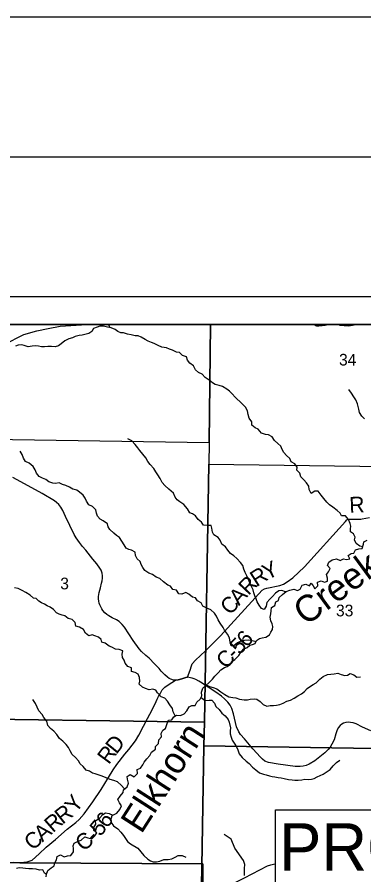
# Model space of a CAD drawing. Extents: x -20.5 to 34, y -66 to 23.9.
# Drawn here: x 5.279 to 6.523, y 18.93 to 22 of the extents above; entities that cross this region are included whole.
import ezdxf

# ---------------------------------------------------------------- set-up
doc = ezdxf.new("R2010")
doc.units = 0
for name, color, linetype in [('Default', 7, 'Continuous'), ('GM_X_County_Road_Text', 7, 'Continuous'), ('GM_X_County_Text', 7, 'Continuous'), ('GM_X_Minor_Lake', 7, 'Continuous'), ('GM_X_Minor_River_Text', 7, 'Continuous'), ('GM_X_State_Route', 7, 'Continuous'), ('GM_X_Township_Road', 7, 'Continuous'), ('GM_X_Township_Road_Text', 7, 'Continuous'), ('GM_X_Township_Text', 7, 'Continuous'), ('SH_Border', 7, 'Continuous'), ('SH_Cut_Line', 7, 'Continuous'), ('SH_Data', 7, 'Continuous'), ('SH_Text', 7, 'Continuous')]:
    doc.layers.add(name, color=color, linetype=linetype)

msp = doc.modelspace()

# ---------------------------------------------------------------- linework, layer by layer
at = {"layer": 'Default'}
for points in [[(2.1, 20.9), (8.9, 20.9), (8.9, 14.1), (2.1, 14.1)], [(5.9729, 20.9), (4.9548, 20.9), (4.9488, 20.4926), (5.968, 20.4777)], [(6.961, 20.9), (5.9729, 20.9), (5.968, 20.4777), (5.9663, 20.3996), (6.9585, 20.3868)]]:
    msp.add_lwpolyline(points, close=True, dxfattribs=at)
for points in [[(8.3774, 18.8452), (8.7292, 18.8379), (8.9, 18.8361), (8.9, 20.9), (2.1, 20.9), (2.1, 19.024), (2.1138, 19.0238), (2.8866, 19.0123), (2.9847, 19.0125), (3.3332, 19.0103), (5.1839, 18.9738), (5.2343, 18.9736), (5.2893, 18.9731), (5.9456, 18.969), (5.9451, 18.8918), (6.0429, 18.8899), (6.0928, 18.889), (6.2064, 18.8869)], [(6.2064, 18.8869), (6.0928, 18.889), (6.0429, 18.8899), (5.9451, 18.8918), (5.9456, 18.969), (5.2893, 18.9731), (5.2343, 18.9736), (5.1839, 18.9738), (3.3332, 19.0103), (2.9847, 19.0125), (2.8866, 19.0123), (2.8861, 18.9025), (2.8826, 18.5075), (2.8801, 18.0269), (2.88, 18.0245)]]:
    msp.add_lwpolyline(points, dxfattribs=at)
at = {"layer": 'GM_X_County_Text'}
for points in [[(4.9459, 20.818), (4.9557, 20.8151), (5.1026, 20.8066), (5.1363, 20.8076), (5.15, 20.8095), (5.2334, 20.8288), (5.3038, 20.8638), (5.3498, 20.8773), (5.3902, 20.8851)], [(5.3902, 20.8851), (5.4336, 20.8934), (5.5299, 20.9)], [(6.345, 20.9), (6.3465, 20.8987), (6.3501, 20.896), (6.3534, 20.8949), (6.3611, 20.895), (6.3729, 20.8959), (6.3834, 20.8976), (6.3946, 20.9)], [(6.4354, 20.898), (6.4688, 20.8956), (6.4949, 20.9)], [(6.0946, 18.9277), (6.0951, 18.9521), (6.0953, 18.9667), (6.0907, 18.9815), (6.0603, 19.0257), (6.0466, 19.0569), (6.0218, 19.0744)]]:
    msp.add_lwpolyline(points, dxfattribs=at)
at = {"layer": 'GM_X_Minor_Lake'}
for points in [[(5.968, 20.4777), (5.9663, 20.3996), (5.9508, 19.4767), (4.9304, 19.491), (4.9488, 20.4926)], [(5.9663, 20.3996), (6.9585, 20.3868), (6.9446, 19.3763), (5.9493, 19.3913), (5.9508, 19.4767)], [(4.9304, 19.491), (5.9508, 19.4767), (5.9493, 19.3913), (5.9332, 18.4574), (4.9118, 18.4742)]]:
    msp.add_lwpolyline(points, close=True, dxfattribs=at)
msp.add_lwpolyline([(6.9358, 18.3792), (6.9356, 18.3607), (5.9313, 18.3709), (5.9332, 18.4574), (5.9493, 19.3913), (6.9446, 19.3763), (6.9427, 19.1628)], dxfattribs=at)
at = {"layer": 'GM_X_Minor_River_Text'}
msp.add_line((5.6113, 20.8889), (5.6088, 20.9), dxfattribs=at)
for points in [[(6.5188, 20.1044), (6.508, 20.1059), (6.4953, 20.1155), (6.489, 20.1295), (6.4919, 20.139), (6.4856, 20.1503), (6.4749, 20.1581), (6.4747, 20.1679), (6.4761, 20.1774), (6.4736, 20.188), (6.4673, 20.2023), (6.4564, 20.2154), (6.4428, 20.2148), (6.4381, 20.2246), (6.4265, 20.2343), (6.4119, 20.2454), (6.3996, 20.2547), (6.3896, 20.2633), (6.3795, 20.2768), (6.3698, 20.2891), (6.3585, 20.3026), (6.3464, 20.3032), (6.334, 20.2946), (6.3261, 20.3093), (6.3252, 20.321), (6.317, 20.3334), (6.307, 20.3439), (6.2962, 20.3539), (6.2933, 20.3679), (6.2825, 20.3784), (6.2838, 20.3886), (6.2752, 20.4014), (6.2622, 20.408), (6.2567, 20.42), (6.2448, 20.4308), (6.2351, 20.4413), (6.2292, 20.4518), (6.2248, 20.4639), (6.2144, 20.4744), (6.2017, 20.4844), (6.1939, 20.4972), (6.1805, 20.5045), (6.1698, 20.5062), (6.1553, 20.5113), (6.1437, 20.5248), (6.1326, 20.5303), (6.1214, 20.54), (6.1209, 20.551), (6.1115, 20.5645), (6.1079, 20.5781), (6.1058, 20.5902), (6.0983, 20.6041), (6.0848, 20.6168), (6.0616, 20.6399), (6.0501, 20.6511), (6.0408, 20.6608), (6.0308, 20.6682), (6.0162, 20.6778), (6.0036, 20.6818), (5.9895, 20.6854), (5.9795, 20.6905), (5.9684, 20.7006), (5.9542, 20.7098), (5.9426, 20.7218), (5.9299, 20.7276), (5.9184, 20.7373), (5.9124, 20.752), (5.899, 20.7613), (5.8901, 20.7721), (5.8865, 20.7838), (5.872, 20.7889), (5.8615, 20.7993), (5.8513, 20.8003), (5.8367, 20.8077), (5.8256, 20.8117), (5.8153, 20.8157), (5.7986, 20.8192), (5.7852, 20.825), (5.7706, 20.8312), (5.7607, 20.8352), (5.7496, 20.84), (5.7385, 20.8463), (5.7247, 20.8547), (5.7132, 20.8591), (5.7022, 20.8597), (5.6885, 20.8625), (5.6755, 20.8653), (5.6606, 20.8696), (5.6508, 20.8702), (5.6408, 20.8746), (5.6312, 20.8817), (5.6163, 20.8879), (5.603, 20.8907), (5.5892, 20.8935), (5.5763, 20.894), (5.5661, 20.8901), (5.5537, 20.8849), (5.5478, 20.8746), (5.5361, 20.8676), (5.5123, 20.8618), (5.5013, 20.8605)], [(5.5013, 20.8605), (5.4873, 20.8573), (5.4775, 20.8522), (5.4647, 20.8485), (5.45, 20.8415), (5.4377, 20.8303), (5.4279, 20.824), (5.4162, 20.8204), (5.4021, 20.8213), (5.39, 20.8211), (5.3775, 20.8201), (5.3668, 20.82), (5.3562, 20.8217), (5.3467, 20.8234), (5.3338, 20.8217), (5.3194, 20.8203), (5.3052, 20.825), (5.2953, 20.8275), (5.2832, 20.8262), (5.2734, 20.8218)], [(6.5254, 20.5622), (6.5158, 20.5719), (6.5068, 20.5851), (6.5047, 20.5972), (6.4998, 20.6161), (6.4939, 20.6304), (6.4865, 20.6413), (6.4787, 20.6544), (6.4686, 20.6668)], [(6.242, 19.9426), (6.2286, 19.9472), (6.2172, 19.947), (6.206, 19.9377), (6.1948, 19.9258), (6.185, 19.9169), (6.175, 19.905), (6.1726, 19.8913), (6.1655, 19.8801), (6.156, 19.883), (6.1478, 19.895), (6.1404, 19.9067), (6.1364, 19.9176), (6.1321, 19.9289), (6.1285, 19.9395), (6.1253, 19.95), (6.1186, 19.9647), (6.1134, 19.9756), (6.1083, 19.9892), (6.1031, 20.0005), (6.0969, 20.0118), (6.0917, 20.0239), (6.0881, 20.0371), (6.0807, 20.0476), (6.0676, 20.0618), (6.0568, 20.0722), (6.0449, 20.08), (6.0344, 20.0916), (6.0266, 20.104), (6.0139, 20.1129), (6.0072, 20.1275), (6.0006, 20.1373), (5.9853, 20.1465), (5.9794, 20.1563), (5.9777, 20.1703), (5.9752, 20.1805), (5.9615, 20.1799), (5.9482, 20.182), (5.9408, 20.1921), (5.9289, 20.2017), (5.9184, 20.2152), (5.9084, 20.2219), (5.8985, 20.2259), (5.8899, 20.2398), (5.8775, 20.2555), (5.8629, 20.2648), (5.8529, 20.2726), (5.8459, 20.2823), (5.8396, 20.2963), (5.8238, 20.3108), (5.8095, 20.3231), (5.7991, 20.3347), (5.7924, 20.3486), (5.7838, 20.3621), (5.7764, 20.3718), (5.7694, 20.3839), (5.7566, 20.3981), (5.7485, 20.4097), (5.7407, 20.4221), (5.7306, 20.4356), (5.719, 20.4483), (5.7123, 20.4584), (5.7026, 20.4708), (5.6903, 20.4835), (5.6765, 20.4908)], [(6.136, 19.7642), (6.1173, 19.7689), (6.1074, 19.7695), (6.0941, 19.7689), (6.0835, 19.7676), (6.0696, 19.7606), (6.0565, 19.7501), (6.0466, 19.7499), (6.043, 19.7628), (6.0412, 19.7779), (6.0338, 19.7914), (6.0225, 19.8057), (6.0178, 19.8155), (6.0069, 19.8312), (5.9999, 19.8429), (5.9943, 19.8557), (5.9866, 19.8665), (5.9738, 19.8785), (5.9593, 19.8847), (5.9451, 19.892), (5.9389, 19.9029), (5.9262, 19.9111), (5.9184, 19.9219), (5.9085, 19.9233), (5.8954, 19.9341), (5.8839, 19.94), (5.8704, 19.934), (5.8593, 19.9361), (5.8504, 19.9493), (5.8374, 19.9506), (5.8292, 19.9637), (5.8197, 19.967), (5.8047, 19.9792), (5.7912, 19.99), (5.7782, 19.9959), (5.7644, 20.0048), (5.7514, 20.0091), (5.7368, 20.0187), (5.7298, 20.0296), (5.7239, 20.0409), (5.7207, 20.0515), (5.7095, 20.0604), (5.704, 20.0724), (5.7027, 20.0849), (5.6893, 20.0923), (5.6797, 20.094), (5.6698, 20.0996), (5.6631, 20.1112), (5.6546, 20.1243), (5.6464, 20.1371), (5.6352, 20.1441), (5.6256, 20.1531), (5.6121, 20.1654), (5.6059, 20.1751), (5.6034, 20.1857), (5.5876, 20.1972), (5.5777, 20.2024), (5.568, 20.2136), (5.564, 20.2245), (5.5612, 20.2366), (5.5496, 20.2486), (5.5366, 20.2544), (5.5276, 20.2672), (5.5232, 20.2785), (5.5166, 20.289), (5.5035, 20.2998), (5.4939, 20.3064), (5.4794, 20.3108), (5.4675, 20.3178), (5.4542, 20.3232), (5.4416, 20.3276), (5.4301, 20.3331), (5.4176, 20.3306), (5.4073, 20.3319), (5.3936, 20.337), (5.3824, 20.3444), (5.3702, 20.3492), (5.3579, 20.3562), (5.349, 20.3682), (5.3439, 20.3791), (5.3372, 20.3919), (5.3226, 20.4038), (5.3096, 20.4096), (5.3018, 20.4209), (5.2978, 20.4341), (5.2907, 20.4469)], [(5.817, 19.4714), (5.8221, 19.4833), (5.8346, 19.4842), (5.8409, 19.4957), (5.8511, 19.5012), (5.8647, 19.5007), (5.8787, 19.5066), (5.8876, 19.517), (5.8961, 19.5308), (5.9059, 19.5355), (5.9177, 19.5357), (5.9236, 19.5483), (5.9352, 19.5584), (5.9422, 19.5702), (5.9404, 19.5831), (5.9447, 19.5976), (5.9556, 19.6077), (5.9679, 19.6185), (5.9799, 19.6308), (5.9884, 19.6404), (6.0004, 19.6528), (6.0101, 19.6632), (6.0229, 19.6718), (6.0327, 19.6761), (6.0428, 19.6823), (6.0483, 19.6923), (6.0596, 19.7008), (6.0738, 19.7147), (6.0804, 19.7243), (6.0912, 19.737), (6.1037, 19.744), (6.1138, 19.7514), (6.1236, 19.7546), (6.1334, 19.7582), (6.1378, 19.7681), (6.1487, 19.7759), (6.1585, 19.7787), (6.1714, 19.7801), (6.1842, 19.7886), (6.1893, 19.7982), (6.1952, 19.8082), (6.1966, 19.8188), (6.1941, 19.8286), (6.1894, 19.8388), (6.1869, 19.852), (6.1886, 19.8646), (6.1899, 19.8745), (6.1912, 19.887), (6.2029, 19.894), (6.2068, 19.907), (6.2166, 19.9117), (6.2191, 19.9224), (6.2307, 19.9332), (6.2442, 19.9444), (6.2574, 19.9492), (6.271, 19.9525), (6.2844, 19.9474), (6.2945, 19.9529), (6.3019, 19.9663), (6.3144, 19.9703), (6.3274, 19.9648), (6.3337, 19.9744), (6.3407, 19.9646), (6.3466, 19.953), (6.3574, 19.9649), (6.3568, 19.9774), (6.3696, 19.9822), (6.3818, 19.9771), (6.392, 19.9814), (6.3922, 19.9913), (6.3886, 20.0053), (6.3956, 20.0149), (6.4019, 20.0263), (6.3926, 20.0368), (6.3966, 20.049), (6.4086, 20.0576), (6.4245, 20.0613), (6.4375, 20.0554), (6.4495, 20.0605), (6.4602, 20.0584), (6.4719, 20.0605), (6.4664, 20.0726), (6.4769, 20.08), (6.4864, 20.0809), (6.493, 20.0931), (6.5047, 20.0971), (6.5169, 20.0977), (6.5212, 20.1129), (6.5222, 20.1224), (6.5346, 20.1272)], [(5.8459, 19.4984), (5.8391, 19.5128), (5.8366, 19.5249), (5.8273, 19.538), (5.8191, 19.5515), (5.8094, 19.562), (5.7953, 19.5674), (5.7833, 19.5809), (5.7763, 19.5906), (5.766, 19.5939), (5.7527, 19.5921), (5.7393, 19.5972), (5.729, 19.602), (5.7171, 19.612), (5.7199, 19.6231), (5.7182, 19.6363), (5.7131, 19.648), (5.7023, 19.6543), (5.6893, 19.6579), (5.6891, 19.6708), (5.6758, 19.6751), (5.6672, 19.6878), (5.6632, 19.698), (5.6574, 19.7082), (5.6557, 19.7195), (5.6581, 19.7317), (5.6455, 19.7368), (5.6326, 19.7374), (5.6195, 19.7451), (5.6092, 19.7487), (5.5954, 19.7591), (5.5832, 19.7623), (5.5811, 19.7722), (5.5715, 19.78), (5.5581, 19.7851), (5.5486, 19.7891), (5.5361, 19.7851), (5.5249, 19.7944), (5.5179, 19.8079), (5.5029, 19.816), (5.4896, 19.8196), (5.4878, 19.8332), (5.4763, 19.844), (5.4629, 19.8476), (5.4506, 19.8573), (5.4411, 19.8594), (5.4304, 19.8634), (5.4208, 19.8681), (5.4096, 19.8797), (5.3973, 19.8879), (5.387, 19.8926), (5.3774, 19.8989), (5.3674, 19.9037), (5.3578, 19.9096), (5.3474, 19.9185), (5.3379, 19.9206), (5.326, 19.9311), (5.3106, 19.9403), (5.2972, 19.9473), (5.2834, 19.9543), (5.2697, 19.9575)], [(5.9575, 19.6094), (5.9689, 19.6045), (5.9823, 19.6005), (5.996, 19.5958), (6.0103, 19.5843), (6.0241, 19.5754), (6.0383, 19.5669), (6.0531, 19.5641), (6.0638, 19.5635), (6.0771, 19.5592), (6.0939, 19.5565), (6.1053, 19.5559), (6.1155, 19.5587), (6.1288, 19.5601), (6.1387, 19.5583), (6.1506, 19.5506), (6.161, 19.5401), (6.1748, 19.5331), (6.1869, 19.5364), (6.1983, 19.5362), (6.2097, 19.5368), (6.221, 19.54), (6.2331, 19.5447), (6.2459, 19.551), (6.2595, 19.555), (6.273, 19.5621), (6.2862, 19.5707), (6.2986, 19.5777), (6.3098, 19.5858), (6.3199, 19.5966), (6.3311, 19.6052), (6.3413, 19.611), (6.3514, 19.6173), (6.3645, 19.6304), (6.3773, 19.6401), (6.3923, 19.6468), (6.4037, 19.6477), (6.4166, 19.6491), (6.4291, 19.6512), (6.4409, 19.6468), (6.4539, 19.6436), (6.4634, 19.6445), (6.4731, 19.65), (6.4865, 19.6461), (6.4973, 19.6379), (6.5102, 19.6381)], [(5.9388, 19.5645), (5.9538, 19.5541), (5.9675, 19.5551), (5.9774, 19.5553), (5.9874, 19.5437), (5.9914, 19.5327), (6.0034, 19.5212), (6.0138, 19.5088), (6.0258, 19.4984), (6.0358, 19.4861), (6.0398, 19.4763)], [(5.39, 19.4639), (5.3855, 19.4802), (5.3755, 19.4933), (5.3692, 19.5034), (5.3572, 19.5169), (5.3517, 19.5301), (5.3458, 19.5429), (5.3353, 19.5571)], [(5.6094, 19.1488), (5.6227, 19.143), (5.6366, 19.1511), (5.6481, 19.1638), (5.6536, 19.1772), (5.6466, 19.1877), (5.64, 19.1994), (5.6493, 19.2109), (5.6593, 19.2243), (5.6614, 19.2346), (5.6734, 19.245), (5.6785, 19.2584), (5.6749, 19.2723), (5.674, 19.2818), (5.6848, 19.2888), (5.699, 19.2803), (5.7113, 19.2926), (5.7095, 19.3063), (5.7223, 19.3118), (5.7297, 19.324), (5.7345, 19.3336), (5.7445, 19.3455), (5.7553, 19.357), (5.7612, 19.3692), (5.775, 19.3801), (5.776, 19.3896), (5.7864, 19.4), (5.7877, 19.4133), (5.7967, 19.424), (5.7961, 19.4362), (5.8016, 19.4476), (5.8117, 19.4531), (5.817, 19.4714)], [(6.0398, 19.4763), (6.044, 19.4559), (6.0427, 19.4448), (6.0428, 19.435), (6.0468, 19.4229), (6.0508, 19.412), (6.0574, 19.4015), (6.0655, 19.3875), (6.0706, 19.3774), (6.0761, 19.3631), (6.0865, 19.3492), (6.1003, 19.3369), (6.1111, 19.3279), (6.1238, 19.3152), (6.1356, 19.3052), (6.149, 19.2955), (6.1627, 19.2896), (6.1722, 19.2875), (6.184, 19.2847), (6.1939, 19.2822), (6.2034, 19.2804), (6.2151, 19.2787), (6.2265, 19.2773), (6.2368, 19.2752), (6.252, 19.2713), (6.2656, 19.2696), (6.2755, 19.2682), (6.2868, 19.2684), (6.3008, 19.2694), (6.3106, 19.2718), (6.3238, 19.2716), (6.3348, 19.2722), (6.3446, 19.2746), (6.3547, 19.2804), (6.366, 19.2848), (6.3765, 19.2903), (6.3878, 19.2976), (6.4016, 19.3073), (6.4124, 19.3204), (6.4247, 19.332), (6.4367, 19.3405)], [(5.6645, 19.2372), (5.6529, 19.2508), (5.6398, 19.2623), (5.6258, 19.267), (5.6132, 19.2706), (5.5991, 19.2765), (5.5839, 19.2827), (5.5732, 19.2871), (5.5592, 19.2918), (5.5493, 19.2943), (5.539, 19.3006), (5.5275, 19.305), (5.5164, 19.3173), (5.5053, 19.327), (5.499, 19.3383), (5.4883, 19.3495), (5.4767, 19.36), (5.4694, 19.3735), (5.4642, 19.3856), (5.455, 19.3964), (5.4438, 19.408), (5.4316, 19.4177), (5.4219, 19.4316), (5.4115, 19.4443), (5.3996, 19.454), (5.39, 19.4639)], [(5.3839, 18.9227), (5.3853, 18.9322), (5.3893, 18.9448), (5.4016, 18.9545), (5.4125, 18.9615), (5.4146, 18.9733), (5.4212, 18.9836), (5.4229, 18.9958), (5.4349, 19.0009), (5.4479, 18.9939), (5.4596, 18.9982), (5.4721, 18.9984), (5.4821, 19.0119), (5.4811, 19.024), (5.4802, 19.0335), (5.4842, 19.043), (5.4978, 19.05), (5.5094, 19.0536), (5.5221, 19.0656), (5.5335, 19.0623), (5.5468, 19.0591), (5.558, 19.0695), (5.5658, 19.0807), (5.5547, 19.0881), (5.5549, 19.0987), (5.5619, 19.1109), (5.561, 19.1227), (5.5759, 19.1343), (5.5867, 19.1462), (5.5965, 19.1513), (5.6094, 19.1488)], [(5.6197, 19.1443), (5.6157, 19.1296), (5.6171, 19.1171), (5.6248, 19.1051), (5.6401, 19.0939), (5.6517, 19.0827), (5.6613, 19.07), (5.6675, 19.0602), (5.6756, 19.0493), (5.686, 19.0411), (5.7119, 19.0248), (5.7224, 19.0125), (5.7339, 18.9994), (5.7481, 18.9856), (5.7577, 18.9797), (5.7672, 18.9768), (5.7789, 18.9762), (5.791, 18.979), (5.8049, 18.9842), (5.8208, 18.9848), (5.8336, 18.9876), (5.846, 18.9935), (5.8573, 18.999), (5.8717, 18.9992), (5.8842, 18.9933)], [(5.3851, 18.931), (5.378, 18.9363), (5.3722, 18.9476), (5.3597, 18.9459), (5.3479, 18.9495), (5.3343, 18.9512), (5.321, 18.9517), (5.3093, 18.9527), (5.2998, 18.9537), (5.2873, 18.9546), (5.2767, 18.9526)]]:
    msp.add_lwpolyline(points, dxfattribs=at)
at = {"layer": 'GM_X_State_Route'}
for points in [[(5.8906, 19.6368), (5.8996, 19.6627), (5.9041, 19.678), (5.9074, 19.6852), (5.919, 19.698), (5.9552, 19.7322), (6.0086, 19.7857), (6.1584, 19.9483), (6.1667, 19.9538), (6.1742, 19.9562), (6.2209, 19.9655), (6.2349, 19.97), (6.248, 19.9782), (6.2675, 19.9934), (6.3098, 20.0319), (6.4566, 20.1944), (6.4621, 20.2006), (6.4644, 20.202), (6.4697, 20.203), (6.5116, 20.2034), (6.5165, 20.204), (6.5423, 20.209)], [(5.2651, 18.9747), (5.2914, 18.9741), (5.3153, 18.9763), (5.3333, 18.9826), (5.3585, 19.0046), (5.384, 19.0289), (5.4176, 19.0566), (5.4583, 19.0934), (5.4905, 19.1177), (5.5023, 19.1279), (5.52, 19.148), (5.5513, 19.1915), (5.5812, 19.2352), (5.6075, 19.2784), (5.6235, 19.3061), (5.6365, 19.3248), (5.6652, 19.3613), (5.6801, 19.3788), (5.704, 19.4097), (5.7161, 19.4294), (5.733, 19.4615), (5.7472, 19.489), (5.7638, 19.5207), (5.7774, 19.5505), (5.7818, 19.5581), (5.7863, 19.5676), (5.7917, 19.5778), (5.7995, 19.5915), (5.8088, 19.601), (5.8207, 19.6094), (5.8478, 19.6263)], [(5.8478, 19.6263), (5.8568, 19.6279), (5.8696, 19.6311), (5.8845, 19.636), (5.8906, 19.6368)], [(6.0422, 18.8887), (6.0431, 18.8894), (6.0615, 18.9024), (6.0945, 18.9196), (6.1772, 18.9617), (6.1887, 18.9656), (6.1991, 18.9679), (6.2064, 18.9689)]]:
    msp.add_lwpolyline(points, dxfattribs=at)
at = {"layer": 'GM_X_Township_Road'}
for points in [[(5.8478, 19.6263), (5.8402, 19.6272), (5.8311, 19.6297), (5.8246, 19.6328), (5.8186, 19.637), (5.8087, 19.6452), (5.7962, 19.6592), (5.7885, 19.668), (5.7725, 19.6856), (5.7524, 19.7049), (5.7414, 19.7149), (5.7259, 19.7292), (5.717, 19.7393), (5.6951, 19.7689), (5.6645, 19.8162), (5.6563, 19.8263), (5.6514, 19.8307), (5.6448, 19.837), (5.6362, 19.8423), (5.62, 19.8501), (5.6082, 19.8566), (5.6015, 19.8614), (5.5936, 19.8682), (5.5871, 19.8755), (5.5832, 19.8814), (5.5803, 19.8867), (5.5761, 19.8959), (5.5738, 19.9025), (5.5723, 19.9089), (5.5714, 19.9176), (5.5714, 19.9267), (5.5737, 19.9401), (5.5784, 19.9575), (5.5822, 19.9735), (5.5848, 19.9824), (5.5856, 19.9913), (5.5851, 19.9998), (5.5839, 20.0094), (5.5804, 20.02), (5.5758, 20.028), (5.565, 20.0435), (5.5513, 20.0603), (5.5253, 20.0924), (5.514, 20.1056), (5.5031, 20.1189), (5.4909, 20.1363), (5.4837, 20.1479), (5.4534, 20.212), (5.4434, 20.2337), (5.4357, 20.2463), (5.4294, 20.2549), (5.4206, 20.2632), (5.4131, 20.2691), (5.3689, 20.2949), (5.3195, 20.3217), (5.2642, 20.3517)], [(5.8906, 19.6368), (5.8845, 19.636), (5.8696, 19.6311), (5.8568, 19.6279), (5.8478, 19.6263)], [(6.5471, 19.4451), (6.5179, 19.4588), (6.4948, 19.4699), (6.484, 19.4736), (6.475, 19.4756), (6.467, 19.4763), (6.4583, 19.4752), (6.4496, 19.4725), (6.444, 19.4695), (6.4375, 19.4641), (6.4303, 19.4558), (6.4255, 19.4455), (6.4223, 19.4346), (6.4159, 19.4135), (6.4083, 19.398), (6.402, 19.3873), (6.395, 19.3782), (6.3826, 19.3669), (6.3463, 19.3384), (6.3266, 19.3258), (6.3152, 19.3207), (6.3053, 19.3188), (6.2939, 19.3173), (6.2767, 19.3181), (6.2154, 19.3265), (6.1806, 19.3323), (6.168, 19.3372), (6.1588, 19.3437), (6.1518, 19.3509), (6.1245, 19.381), (6.0947, 19.4164), (6.0801, 19.4321), (6.0746, 19.4421), (6.0658, 19.4599), (6.0558, 19.5057), (6.0497, 19.5253), (6.0432, 19.5373), (6.0349, 19.5481), (6.0282, 19.5551), (6.0231, 19.56), (6.0118, 19.5697), (5.992, 19.5836), (5.9647, 19.6013), (5.9549, 19.6075), (5.9428, 19.6154), (5.9305, 19.6228), (5.9199, 19.6287), (5.9142, 19.6316), (5.9075, 19.6338), (5.9008, 19.6355), (5.8906, 19.6368)]]:
    msp.add_lwpolyline(points, dxfattribs=at)
at = {"layer": 'SH_Border'}
msp.add_lwpolyline([(1.5, 21.5), (33.5, 21.5), (33.5, 0.5), (1.5, 0.5)], close=True, dxfattribs=at)
at = {"layer": 'SH_Cut_Line'}
msp.add_lwpolyline([(0, 0), (34, 0), (34, 22), (0, 22)], close=True, dxfattribs=at)
msp.add_lwpolyline([(8.0662, 14.9881), (8.0784, 15.8902), (8.0825, 16.3121), (8.087, 16.6605), (8.0955, 17.3258), (8.2289, 17.3235), (8.271, 17.3227), (8.5216, 17.3182), (8.9, 17.3115), (8.9, 20.9), (2.1, 20.9), (2.1, 14.4131)], dxfattribs=at)
at = {"layer": 'SH_Data'}
for p, q in [((2, 21), (9, 21)), ((2.1, 20.9), (8.9, 20.9))]:
    msp.add_line(p, q, dxfattribs=at)
at = {"layer": 'SH_Text'}
msp.add_lwpolyline([(6.2064, 19.1628), (8.3774, 19.1628), (8.3774, 18.3792), (6.2064, 18.3792)], close=True, dxfattribs=at)

# ---------------------------------------------------------------- texts
at = {"layer": 'GM_X_County_Road_Text'}
for s, height, rotation, p in [('Creek', 0.0947, 36.301, (6.3146, 19.819)), ('Elkhorn', 0.09469, 57.285, (5.7248, 19.073))]:
    msp.add_text(s, height=height, rotation=rotation, dxfattribs=at).set_placement(p)
at = {"layer": 'GM_X_Township_Road_Text'}
for s, rotation, p in [('R', 2.1276, (6.4712, 20.2256)), ('Y', 26.3337, (6.1758, 19.9836)), ('R', 32.4365, (6.1378, 19.9593)), ('R', 46.7914, (6.1088, 19.9277)), ('C', 47.3285, (6.0434, 19.8568)), ('A', 47.3227, (6.075, 19.8911)), ('6', 47.4457, (6.1021, 19.7414)), ('5', 46.6252, (6.0775, 19.7153)), ('C', 45.1118, (6.0271, 19.6643)), ('-', 45.8327, (6.0606, 19.6979)), ('D', 51.2446, (5.6354, 19.3592)), ('R', 53.4509, (5.608, 19.3221)), ('Y', 51.9226, (5.4895, 19.1479)), ('R', 38.0573, (5.4422, 19.1085)), ('R', 40.984, (5.4075, 19.0784)), ('5', 49.963, (5.5777, 19.0646)), ('6', 52.9164, (5.6022, 19.0939)), ('A', 41.4573, (5.3702, 19.0454)), ('C', 41.4639, (5.3352, 19.0145)), ('C', 40.2103, (5.5175, 19.0111)), ('-', 42.8991, (5.5553, 19.0431))]:
    msp.add_text(s, height=0.0568, rotation=rotation, dxfattribs=at).set_placement(p)
at = {"layer": 'GM_X_Township_Text'}
for s, height, p in [('34', 0.04186, (6.4335, 20.7529)), ('3', 0.0419, (5.434, 19.9517)), ('33', 0.04186, (6.4227, 19.855))]:
    msp.add_text(s, height=height, rotation=0, dxfattribs=at).set_placement(p)
at = {"layer": 'SH_Text'}
msp.add_text('PROJECT LOCATION ', height=0.17, dxfattribs=at).set_placement((6.2187, 18.9442))

doc.saveas('drawing.dxf')
